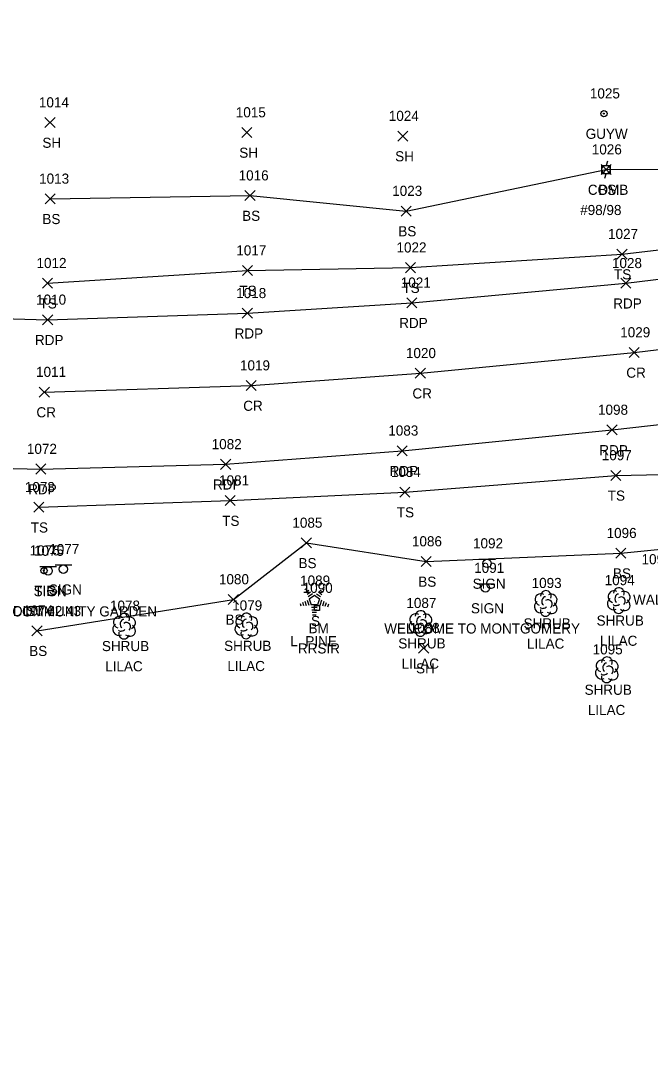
# Model space of a CAD drawing. Extents: x 1600395 to 1603269, y 874955 to 877143.
# Drawn here: x 1601502 to 1601626.7, y 875076 to 875283.1 of the extents above; entities that cross this region are included whole.
import ezdxf

# ---------------------------------------------------------------- set-up
doc = ezdxf.new("R2010")
doc.units = 0
for name, color, linetype in [('C_A', 7, 'Continuous'), ('C_C', 7, 'Continuous'), ('C_I', 7, 'Continuous'), ('CBP', 7, 'Continuous'), ('CPBM', 7, 'Continuous'), ('L_A', 7, 'Continuous'), ('L_C', 7, 'Continuous'), ('L_I', 7, 'Continuous'), ('L_TIC', 7, 'Continuous'), ('LELB', 7, 'Continuous'), ('LSH', 7, 'Continuous'), ('LTC', 7, 'Continuous'), ('P_A', 7, 'Continuous'), ('P_I', 7, 'Continuous'), ('P_TIC', 7, 'Continuous'), ('PET', 7, 'Continuous'), ('PRC', 7, 'Continuous'), ('S_A', 7, 'Continuous'), ('S_C', 7, 'Continuous'), ('S_I', 7, 'Continuous'), ('SSGN', 7, 'Continuous'), ('U_A', 7, 'Continuous'), ('U_C', 7, 'Continuous'), ('U_I', 7, 'Continuous'), ('UP', 7, 'Continuous'), ('UPGW', 7, 'Continuous')]:
    doc.layers.add(name, color=color, linetype=linetype)

msp = doc.modelspace()

# ---------------------------------------------------------------- linework, layer by layer
at = {"layer": 'CBP'}
for radius in [0.625, 0.0833]:
    msp.add_circle((1601506.6, 875174.31), radius, dxfattribs=at)
at = {"layer": 'CPBM'}
for p, q in [((1601560.19, 875166.4), (1601560.19, 875167.4)), ((1601560.19, 875167.4), (1601561.19, 875167.4)), ((1601561.19, 875167.4), (1601561.19, 875166.4)), ((1601561.19, 875166.4), (1601560.19, 875166.4)), ((1601560.7, 875166.9), (1601560.7, 875166.9)), ((1601560.7, 875166.9), (1601560.7, 875166.9))]:
    msp.add_line(p, q, dxfattribs=at)
at = {"layer": 'L_TIC'}
for points in [[(1601506.8, 875261.99), (1601508.8, 875263.99)], [(1601508.8, 875261.99), (1601506.8, 875263.99)], [(1601545.8, 875260.02), (1601547.8, 875262.02)], [(1601547.8, 875260.02), (1601545.8, 875262.02)], [(1601576.69, 875259.31), (1601578.69, 875261.31)], [(1601578.69, 875259.31), (1601576.69, 875261.31)], [(1601616.95, 875252.68), (1601618.95, 875254.68)], [(1601618.95, 875252.68), (1601616.95, 875254.68)], [(1601506.85, 875246.89), (1601508.85, 875248.89)], [(1601508.85, 875246.89), (1601506.85, 875248.89)], [(1601546.42, 875247.53), (1601548.42, 875249.53)], [(1601548.42, 875247.53), (1601546.42, 875249.53)], [(1601577.35, 875244.47), (1601579.35, 875246.47)], [(1601579.35, 875244.47), (1601577.35, 875246.47)], [(1601620.11, 875235.95), (1601622.11, 875237.95)], [(1601622.11, 875235.95), (1601620.11, 875237.95)], [(1601545.9, 875232.69), (1601547.9, 875234.69)], [(1601547.9, 875232.69), (1601545.9, 875234.69)], [(1601578.2, 875233.27), (1601580.2, 875235.27)], [(1601580.2, 875233.27), (1601578.2, 875235.27)], [(1601506.32, 875230.19), (1601508.32, 875232.19)], [(1601508.32, 875230.19), (1601506.32, 875232.19)], [(1601618.87, 875192.15), (1601620.87, 875194.15)], [(1601620.87, 875192.15), (1601618.87, 875194.15)], [(1601577.09, 875188.84), (1601579.09, 875190.84)], [(1601579.09, 875188.84), (1601577.09, 875190.84)], [(1601504.58, 875185.84), (1601506.58, 875187.84)], [(1601506.58, 875185.84), (1601504.58, 875187.84)], [(1601542.5, 875187.16), (1601544.5, 875189.16)], [(1601544.5, 875187.16), (1601542.5, 875189.16)], [(1601557.58, 875178.79), (1601559.58, 875180.79)], [(1601559.58, 875178.79), (1601557.58, 875180.79)], [(1601619.87, 875176.75), (1601621.87, 875178.75)], [(1601621.87, 875176.75), (1601619.87, 875178.75)], [(1601581.31, 875175.11), (1601583.31, 875177.11)], [(1601583.31, 875175.11), (1601581.31, 875177.11)], [(1601543.12, 875167.6), (1601545.12, 875169.6)], [(1601545.12, 875167.6), (1601543.12, 875169.6)], [(1601504.23, 875161.4), (1601506.23, 875163.4)], [(1601506.23, 875161.4), (1601504.23, 875163.4)], [(1601580.82, 875157.96), (1601582.82, 875159.96)], [(1601582.82, 875157.96), (1601580.82, 875159.96)]]:
    msp.add_lwpolyline(points, dxfattribs=at)
at = {"layer": 'LELB'}
for points in [[(1601507.85, 875247.89), (1601547.42, 875248.53), (1601578.35, 875245.47), (1601617.95, 875253.68), (1601656.94, 875253.77), (1601694.04, 875267.34), (1601727.19, 875283.1)], [(1601507.32, 875231.19), (1601546.9, 875233.69), (1601579.2, 875234.27), (1601621.11, 875236.95), (1601658.66, 875241.36), (1601694.78, 875245.5), (1601700.77, 875248.82), (1601715.03, 875250.03), (1601725.08, 875252.01), (1601746.27, 875257.43)], [(1601505.58, 875186.84), (1601543.5, 875188.16), (1601578.09, 875189.84), (1601619.87, 875193.15), (1601653.33, 875193.86), (1601668.35, 875196.11), (1601673.88, 875189.56), (1601676.77, 875181.49), (1601678.04, 875161.08), (1601676.09, 875147.88), (1601668.38, 875110.49), (1601657.67, 875076.04)], [(1601505.23, 875162.4), (1601544.12, 875168.6), (1601558.58, 875179.79), (1601582.31, 875176.11), (1601620.87, 875177.75), (1601653.84, 875181.08), (1601671.17, 875181.13), (1601672.7, 875160.58), (1601672.89, 875148.09), (1601664.48, 875114.32), (1601659.55, 875083.82), (1601652.57, 875078.37)]]:
    msp.add_lwpolyline(points, dxfattribs=at)
at = {"layer": 'LSH'}
for p, q in [((1601605.97, 875167.86), (1601605.97, 875167.86)), ((1601605.97, 875167.86), (1601605.97, 875167.86)), ((1601620.44, 875168.42), (1601620.44, 875168.42)), ((1601620.44, 875168.42), (1601620.44, 875168.42)), ((1601522.45, 875163.37), (1601522.45, 875163.37)), ((1601522.45, 875163.37), (1601522.45, 875163.37)), ((1601546.66, 875163.42), (1601546.66, 875163.42)), ((1601546.66, 875163.42), (1601546.66, 875163.42)), ((1601581.16, 875163.9), (1601581.16, 875163.9)), ((1601581.16, 875163.9), (1601581.16, 875163.9)), ((1601618.06, 875154.72), (1601618.06, 875154.72)), ((1601618.06, 875154.72), (1601618.06, 875154.72))]:
    msp.add_line(p, q, dxfattribs=at)
for centre in [(1601606.02, 875169.29), (1601620.49, 875169.86), (1601522.5, 875164.8), (1601546.71, 875164.85), (1601581.21, 875165.33), (1601618.11, 875156.16)]:
    msp.add_arc(centre, 1.05, 335.5272, 180.9563, dxfattribs=at)
for centre, major_axis, ratio, start_param, end_param in [((1601605.18, 875168.52), (1.21, -0.51), 0.895232, 1.570796, 4.712389), ((1601605.76, 875168.31), (-0.208, -0.792), 0.645439, 3.141593, 6.283185), ((1601607.01, 875168.44), (-1.14, -0.48), 0.949671, 1.570796, 4.712389), ((1601619.65, 875169.09), (1.21, -0.51), 0.895232, 1.570796, 4.712389), ((1601620.23, 875168.88), (-0.208, -0.792), 0.645439, 3.141593, 6.283185), ((1601620.94, 875168.26), (-0.5, 0.667), 0.989748, 3.141593, 6.283185), ((1601621.48, 875169.01), (-1.14, -0.48), 0.949671, 1.570796, 4.712389), ((1601604.89, 875167.15), (0.58, -1.04), 0.959034, 3.141593, 6.283185), ((1601605.51, 875167.11), (-0.625, -0.083), 0.423636, 0, 3.141593), ((1601606.47, 875167.69), (-0.5, 0.667), 0.989748, 3.141593, 6.283185), ((1601606.97, 875167.02), (-1.09, 0.79), 0.841452, 1.570796, 4.712389), ((1601619.36, 875167.72), (0.58, -1.04), 0.959034, 3.141593, 6.283185), ((1601620.44, 875166.92), (0.26, 1.06), 0.942809, 1.570796, 4.712389), ((1601619.98, 875167.67), (-0.625, -0.083), 0.423636, 0, 3.141593), ((1601621.44, 875167.59), (-1.09, 0.79), 0.841452, 1.570796, 4.712389), ((1601521.66, 875164.03), (1.21, -0.51), 0.895232, 1.570796, 4.712389), ((1601523.49, 875163.95), (-1.14, -0.48), 0.949671, 1.570796, 4.712389), ((1601545.87, 875164.08), (1.21, -0.51), 0.895232, 1.570796, 4.712389), ((1601547.7, 875164), (-1.14, -0.48), 0.949671, 1.570796, 4.712389), ((1601580.37, 875164.56), (1.21, -0.51), 0.895232, 1.570796, 4.712389), ((1601580.95, 875164.35), (-0.208, -0.792), 0.645439, 3.141593, 6.283185), ((1601582.2, 875164.48), (-1.14, -0.48), 0.949671, 1.570796, 4.712389), ((1601605.97, 875166.36), (0.26, 1.06), 0.942809, 1.570796, 4.712389), ((1601521.37, 875162.66), (0.58, -1.04), 0.959034, 3.141593, 6.283185), ((1601522.24, 875163.83), (-0.208, -0.792), 0.645439, 3.141593, 6.283185), ((1601522.95, 875163.2), (-0.5, 0.667), 0.989748, 3.141593, 6.283185), ((1601523.45, 875162.53), (-1.09, 0.79), 0.841452, 1.570796, 4.712389), ((1601545.58, 875162.71), (0.58, -1.04), 0.959034, 3.141593, 6.283185), ((1601546.45, 875163.87), (-0.208, -0.792), 0.645439, 3.141593, 6.283185), ((1601547.16, 875163.25), (-0.5, 0.667), 0.989748, 3.141593, 6.283185), ((1601547.66, 875162.58), (-1.09, 0.79), 0.841452, 1.570796, 4.712389), ((1601580.08, 875163.19), (0.58, -1.04), 0.959034, 3.141593, 6.283185), ((1601580.7, 875163.15), (-0.625, -0.083), 0.423636, 0, 3.141593), ((1601581.66, 875163.73), (-0.5, 0.667), 0.989748, 3.141593, 6.283185), ((1601582.16, 875163.06), (-1.09, 0.79), 0.841452, 1.570796, 4.712389), ((1601522.45, 875161.87), (0.26, 1.06), 0.942809, 1.570796, 4.712389), ((1601521.99, 875162.62), (-0.625, -0.083), 0.423636, 0, 3.141593), ((1601546.66, 875161.92), (0.26, 1.06), 0.942809, 1.570796, 4.712389), ((1601546.2, 875162.67), (-0.625, -0.083), 0.423636, 0, 3.141593), ((1601581.16, 875162.4), (0.26, 1.06), 0.942809, 1.570796, 4.712389), ((1601617.27, 875155.39), (1.21, -0.51), 0.895232, 1.570796, 4.712389), ((1601616.98, 875154.01), (0.58, -1.04), 0.959034, 3.141593, 6.283185), ((1601617.85, 875155.18), (-0.208, -0.792), 0.645439, 3.141593, 6.283185), ((1601618.56, 875154.56), (-0.5, 0.667), 0.989748, 3.141593, 6.283185), ((1601619.06, 875153.89), (-1.09, 0.79), 0.841452, 1.570796, 4.712389), ((1601619.1, 875155.31), (-1.14, -0.48), 0.949671, 1.570796, 4.712389), ((1601618.06, 875153.22), (0.26, 1.06), 0.942809, 1.570796, 4.712389), ((1601617.6, 875153.97), (-0.625, -0.083), 0.423636, 0, 3.141593)]:
    msp.add_ellipse(centre, major_axis=major_axis, ratio=ratio, start_param=start_param, end_param=end_param, dxfattribs=at)
at = {"layer": 'LTC'}
for p, q in [((1601558.31, 875170.54), (1601558.67, 875170.8)), ((1601558.52, 875170.08), (1601559.05, 875170.46)), ((1601558.73, 875169.61), (1601559.43, 875170.12)), ((1601558.94, 875169.15), (1601559.82, 875169.78)), ((1601559.16, 875168.69), (1601560.18, 875169.43)), ((1601560.18, 875169.43), (1601561.17, 875168.7)), ((1601560.6, 875169.74), (1601561.41, 875169.15)), ((1601560.97, 875170.09), (1601561.65, 875169.59)), ((1601561.34, 875170.43), (1601561.89, 875170.04)), ((1601561.71, 875170.78), (1601562.13, 875170.48)), ((1601557.34, 875167.82), (1601557.5, 875167.35)), ((1601557.8, 875168.04), (1601558.01, 875167.39)), ((1601558.25, 875168.26), (1601558.53, 875167.42)), ((1601558.71, 875168.47), (1601559.04, 875167.45)), ((1601559.16, 875168.69), (1601559.55, 875167.5)), ((1601560.78, 875167.5), (1601559.55, 875167.5)), ((1601561.17, 875168.7), (1601560.78, 875167.5)), ((1601561.61, 875168.43), (1601561.27, 875167.39)), ((1601562.06, 875168.18), (1601561.77, 875167.29)), ((1601562.5, 875167.93), (1601562.26, 875167.2)), ((1601562.94, 875167.68), (1601562.76, 875167.1)), ((1601560.74, 875167), (1601559.6, 875167)), ((1601560.66, 875166.5), (1601559.67, 875166.5)), ((1601560.58, 875166), (1601559.74, 875166)), ((1601560.49, 875165.5), (1601559.82, 875165.5))]:
    msp.add_line(p, q, dxfattribs=at)
at = {"layer": 'P_TIC'}
for points in [[(1601620.88, 875230.18), (1601622.88, 875232.18)], [(1601622.88, 875230.18), (1601620.88, 875232.18)], [(1601578.48, 875226.32), (1601580.48, 875228.32)], [(1601580.48, 875226.32), (1601578.48, 875228.32)], [(1601545.89, 875224.24), (1601547.89, 875226.24)], [(1601547.89, 875224.24), (1601545.89, 875226.24)], [(1601506.33, 875222.94), (1601508.33, 875224.94)], [(1601508.33, 875222.94), (1601506.33, 875224.94)], [(1601622.53, 875216.48), (1601624.53, 875218.48)], [(1601624.53, 875216.48), (1601622.53, 875218.48)], [(1601580.16, 875212.37), (1601582.16, 875214.37)], [(1601582.16, 875212.37), (1601580.16, 875214.37)], [(1601505.67, 875208.64), (1601507.67, 875210.64)], [(1601507.67, 875208.64), (1601505.67, 875210.64)], [(1601546.64, 875209.93), (1601548.64, 875211.93)], [(1601548.64, 875209.93), (1601546.64, 875211.93)], [(1601618.13, 875201.15), (1601620.13, 875203.15)], [(1601620.13, 875201.15), (1601618.13, 875203.15)], [(1601576.58, 875197.03), (1601578.58, 875199.03)], [(1601578.58, 875197.03), (1601576.58, 875199.03)], [(1601541.59, 875194.34), (1601543.59, 875196.34)], [(1601543.59, 875194.34), (1601541.59, 875196.34)], [(1601504.99, 875193.41), (1601506.99, 875195.41)], [(1601506.99, 875193.41), (1601504.99, 875195.41)]]:
    msp.add_lwpolyline(points, dxfattribs=at)
at = {"layer": 'PET'}
for points in [[(1601414.03, 875231.87), (1601447.66, 875227.34), (1601480.39, 875224.74), (1601507.33, 875223.94), (1601546.89, 875225.24), (1601579.48, 875227.32), (1601621.88, 875231.18), (1601659.14, 875235.73), (1601695.51, 875240.66), (1601718.89, 875244.21), (1601760.24, 875249.95), (1601754.15, 875234.47), (1601747.53, 875218.62)], [(1601408.55, 875202.72), (1601438.2, 875198.66), (1601469.02, 875195.65), (1601497.71, 875194.55), (1601505.99, 875194.41), (1601542.59, 875195.34), (1601577.58, 875198.03), (1601619.13, 875202.15), (1601655.31, 875206.25), (1601695.28, 875211.43), (1601717.66, 875214.5), (1601739.73, 875217.72), (1601747.53, 875218.62)]]:
    msp.add_lwpolyline(points, dxfattribs=at)
at = {"layer": 'PRC'}
msp.add_lwpolyline([(1601506.67, 875209.64), (1601547.64, 875210.93), (1601581.16, 875213.37), (1601623.53, 875217.48), (1601660.5, 875221.97), (1601694.05, 875226.22), (1601722.77, 875230.16), (1601754.15, 875234.47)], dxfattribs=at)
at = {"layer": 'SSGN'}
for p, q in [((1601508.79, 875175.43), (1601512.12, 875175.43)), ((1601592.73, 875176.56), (1601596.06, 875176.56)), ((1601594.38, 875175.73), (1601594.38, 875175.73)), ((1601505.77, 875175.09), (1601509.11, 875175.09)), ((1601507.42, 875174.25), (1601507.42, 875174.25)), ((1601510.44, 875174.59), (1601510.44, 875174.59)), ((1601592.4, 875171.71), (1601595.73, 875171.71)), ((1601594.05, 875170.88), (1601594.05, 875170.88))]:
    msp.add_line(p, q, dxfattribs=at)
for centre in [(1601510.44, 875174.59), (1601594.38, 875175.73), (1601507.42, 875174.25), (1601594.05, 875170.88)]:
    msp.add_circle(centre, 0.833, dxfattribs=at)
at = {"layer": 'UP'}
for p, q in [((1601617.12, 875252.84), (1601617.12, 875254.51)), ((1601617.12, 875254.51), (1601618.78, 875254.51)), ((1601618.2, 875255.34), (1601617.95, 875254.51)), ((1601618.78, 875254.51), (1601618.78, 875252.84)), ((1601618.78, 875252.84), (1601617.12, 875252.84)), ((1601617.7, 875252.01), (1601617.95, 875252.84)), ((1601617.95, 875253.68), (1601617.95, 875253.68))]:
    msp.add_line(p, q, dxfattribs=at)
msp.add_circle((1601617.95, 875253.68), 0.833, dxfattribs=at)
at = {"layer": 'UPGW'}
for radius in [0.625, 0.0833]:
    msp.add_circle((1601617.52, 875264.76), radius, dxfattribs=at)

# ---------------------------------------------------------------- texts
at = {"layer": 'C_A'}
for s, p in [('TIE', (1601504.67, 875169.31)), ('BM', (1601559.01, 875161.9))]:
    msp.add_text(s, height=2, dxfattribs=at).set_placement(p)
at = {"layer": 'C_C'}
for s, p in [('TIE DIST 62.43', (1601495.53, 875165.31)), ('RRSIR', (1601556.91, 875157.9))]:
    msp.add_text(s, height=2, dxfattribs=at).set_placement(p)
at = {"layer": 'C_I'}
for s, p in [('1076', (1601503.77, 875177.31)), ('1090', (1601557.84, 875169.9))]:
    msp.add_text(s, height=2, dxfattribs=at).set_placement(p)
at = {"layer": 'L_A'}
for s, p in [('SH', (1601506.29, 875257.99)), ('SH', (1601545.29, 875256.02)), ('SH', (1601576.17, 875255.31)), ('BS', (1601616.39, 875248.68)), ('BS', (1601506.29, 875242.89)), ('BS', (1601545.86, 875243.53)), ('BS', (1601576.79, 875240.47)), ('TS', (1601619.52, 875231.95)), ('TS', (1601577.61, 875229.27)), ('TS', (1601545.31, 875228.69)), ('TS', (1601505.73, 875226.19)), ('TS', (1601618.28, 875188.15)), ('TS', (1601576.5, 875184.84)), ('TS', (1601503.99, 875181.84)), ('TS', (1601541.91, 875183.16)), ('BS', (1601557.02, 875174.79)), ('BS', (1601619.32, 875172.75)), ('BS', (1601580.75, 875171.11)), ('WALLS', (1601623.3, 875167.56)), ('BS', (1601542.56, 875163.6)), ('S', (1601559.5, 875163.33)), ('SHRUB', (1601616.07, 875163.42)), ('SHRUB', (1601601.6, 875162.86)), ('SHRUB', (1601576.79, 875158.9)), ('BS', (1601503.68, 875157.4)), ('SHRUB', (1601518.08, 875158.37)), ('SHRUB', (1601542.29, 875158.42)), ('SH', (1601580.31, 875153.96)), ('SHRUB', (1601613.69, 875149.72))]:
    msp.add_text(s, height=2, dxfattribs=at).set_placement(p)
at = {"layer": 'L_C'}
for s, p in [('L. PINE', (1601555.41, 875159.33)), ('LILAC', (1601602.25, 875158.86)), ('LILAC', (1601616.72, 875159.42)), ('LILAC', (1601577.44, 875154.9)), ('LILAC', (1601518.73, 875154.37)), ('LILAC', (1601542.94, 875154.42)), ('LILAC', (1601614.33, 875145.72))]:
    msp.add_text(s, height=2, dxfattribs=at).set_placement(p)
at = {"layer": 'L_I'}
for s, p in [('1014', (1601505.6, 875265.99)), ('1015', (1601544.6, 875264.02)), ('1024', (1601574.91, 875263.31)), ('1026', (1601615.12, 875256.68)), ('1013', (1601505.64, 875250.89)), ('1016', (1601545.16, 875251.53)), ('1023', (1601575.58, 875248.47)), ('1027', (1601618.34, 875239.95)), ('1017', (1601544.7, 875236.69)), ('1022', (1601576.43, 875237.27)), ('1012', (1601505.12, 875234.19)), ('1097', (1601617.1, 875196.15)), ('1084', (1601575.31, 875192.84)), ('1081', (1601541.29, 875191.16)), ('1073', (1601502.81, 875189.84)), ('1085', (1601555.81, 875182.79)), ('1096', (1601618.05, 875180.75)), ('1086', (1601579.49, 875179.11)), ('1099', (1601624.98, 875175.56)), ('1080', (1601541.26, 875171.6)), ('1089', (1601557.34, 875171.33)), ('1094', (1601617.67, 875171.42)), ('1093', (1601603.2, 875170.86)), ('1074', (1601502.46, 875165.4)), ('1078', (1601519.68, 875166.37)), ('1079', (1601543.88, 875166.42)), ('1087', (1601578.39, 875166.9)), ('1088', (1601579.05, 875161.96)), ('1095', (1601615.29, 875157.72))]:
    msp.add_text(s, height=2, dxfattribs=at).set_placement(p)
at = {"layer": 'LTC'}
msp.add_text('.', height=1.04, rotation=270, dxfattribs=at).set_placement((1601560.06, 875168.44))
at = {"layer": 'P_A'}
for s, p in [('RDP', (1601619.37, 875226.18)), ('RDP', (1601576.97, 875222.32)), ('RDP', (1601504.82, 875218.94)), ('RDP', (1601544.37, 875220.24)), ('CR', (1601621.96, 875212.48)), ('CR', (1601579.59, 875208.37)), ('CR', (1601505.11, 875204.64)), ('CR', (1601546.08, 875205.93)), ('RDP', (1601616.61, 875197.15)), ('RDP', (1601575.07, 875193.03)), ('RDP', (1601540.08, 875190.34)), ('RDP', (1601503.48, 875189.41))]:
    msp.add_text(s, height=2, dxfattribs=at).set_placement(p)
at = {"layer": 'P_I'}
for s, p in [('1028', (1601619.11, 875234.18)), ('1021', (1601577.28, 875230.32)), ('1018', (1601544.68, 875228.24)), ('1010', (1601505.04, 875226.94)), ('1029', (1601620.75, 875220.48)), ('1020', (1601578.3, 875216.37)), ('1011', (1601505.04, 875212.64)), ('1019', (1601545.43, 875213.93)), ('1098', (1601616.35, 875205.15)), ('1083', (1601574.81, 875201.03)), ('1082', (1601539.82, 875198.34)), ('1072', (1601503.22, 875197.41))]:
    msp.add_text(s, height=2, dxfattribs=at).set_placement(p)
at = {"layer": 'S_A'}
for p in [(1601504.56, 875169.23), (1601507.58, 875169.57), (1601591.52, 875170.71), (1601591.18, 875165.85)]:
    msp.add_text('SIGN', height=2, dxfattribs=at).set_placement(p)
at = {"layer": 'S_C'}
for s, p in [('RIVER WALK COMMUNITY GARDEN', (1601483.09, 875165.23)), ('WELCOME TO MONTGOMERY', (1601574.01, 875161.85))]:
    msp.add_text(s, height=2, dxfattribs=at).set_placement(p)
at = {"layer": 'S_I'}
for s, p in [('1077', (1601507.65, 875177.57)), ('1092', (1601591.59, 875178.71)), ('1075', (1601504.63, 875177.23)), ('1091', (1601591.82, 875173.85))]:
    msp.add_text(s, height=2, dxfattribs=at).set_placement(p)
at = {"layer": 'U_A'}
for s, p in [('GUYW', (1601613.91, 875259.76)), ('COMB', (1601614.34, 875248.68))]:
    msp.add_text(s, height=2, dxfattribs=at).set_placement(p)
at = {"layer": 'U_C'}
msp.add_text('#98/98', height=2, dxfattribs=at).set_placement((1601612.82, 875244.68))
at = {"layer": 'U_I'}
for s, p in [('1025', (1601614.74, 875267.76)), ('1026', (1601615.12, 875256.68))]:
    msp.add_text(s, height=2, dxfattribs=at).set_placement(p)

doc.saveas('drawing.dxf')
